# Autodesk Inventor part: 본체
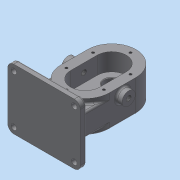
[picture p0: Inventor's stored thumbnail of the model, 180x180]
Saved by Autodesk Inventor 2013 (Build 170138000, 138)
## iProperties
Created: 2020-09
Part Number: 본체
Material: Generic
Document SubType Name: Modeling
Designer: Administrator
Density: 1 g/cm^3
Author: Administrator
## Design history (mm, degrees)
sketch "스케치1"
  geometry: L1 (-40, -62)-(40, -62); L2 (40, -62)-(40, 62); L3 (40, 62)-(-40, 62); L4 (-40, 62)-(-40, -62); L5 (-40, -62)-(40, 62); L6 (40, -62)-(-40, 62); 3 further points
  constraints: 12 end point, 3 midpoint, 2 parallel, 1 coincident, 1 horizontal, 1 perpendicular
  dimensions: "d0" = 124 distance of L1.end L2.end; "d2" = 80 distance of L1.start L1.end
extrude "돌출1" new body sketch "스케치1" distance "d3" = 53; taper "d4" = 0 deg
fillet "모깎기1" dims "d5" = 40
sketch "스케치2"
  geometry: L1 (0, 22)-(0, -22); L2 (24, 22)-(24, -22); L3 (-24, -22)-(-24, 22); A1 r 24 centre (0, -22) between (-24, -22) and (24, -22); A2 r 24 centre (0, 22) between (24, 22) and (-24, 22); 2 further points
  constraints: 6 end point, 4 point on circle, 3 coincident, 2 centre point, 2 parallel, 2 tangent, 1 midpoint, 1 vertical
  dimensions: "d7" = 44 distance of L1.start L1.end
extrude "돌출2" cut sketch "스케치2" distance "d11" = 29; taper "d12" = 0 deg
sketch "스케치3"
  geometry: L1 (-53, 44)-(0, 44) reference; L2 (0, 0)-(0, 44) reference; L3 (-53, 0)-(-53, 44) reference; C1 r 11 at (-39, 22); 3 further points
  constraints: 2 midpoint, 1 centre point, 1 horizontal alignment
  dimensions: "d13" = 22 diameter of C1; "d63" = 14 distance from line of L3 C1.centre
extrude "돌출3" join sketch "스케치3" distance "d15" = 10; taper "d16" = 0 deg
sketch "스케치4"
  geometry: L1 (0, 44)-(53, 44) reference; L2 (0, 44)-(0, 0) reference; L3 (53, 44)-(53, 0) reference; C1 r 11 at (39, 22); 3 further points
  constraints: 2 midpoint, 1 centre point, 1 horizontal alignment
  dimensions: "d17" = 22 diameter of C1; "d64" = 14 distance from line of L3 C1.centre
extrude "돌출4" join sketch "스케치4" distance "d19" = 10; taper "d20" = 0 deg
sketch "스케치5"
  geometry: L1 (-40, -22)-(-40, 22) reference; L2 (-40, 0)-(39.368, 0); C1 r 19 at (0, 22); 1 further point
  constraints: 2 end point, 1 centre point, 1 midpoint, 1 perpendicular
  dimensions: "d21" = 38 diameter of C1; "d23" = 22 distance from line of C1.centre L2
extrude "돌출5" join sketch "스케치5" distance "d24" = 17; taper "d25" = 0 deg
node "작업 평면1"
sketch "스케치6"
  geometry: L1 (-19, -17)-(19, -17) reference; L2 (-60, 83)-(-60, -17); L3 (-60, -17)-(60, -17); L4 (60, -17)-(60, 83); L5 (60, 83)-(-60, 83); L6 (-60, 83)-(60, -17); L7 (-60, -17)-(60, 83); 5 further points
  constraints: 12 end point, 5 midpoint, 2 parallel, 2 perpendicular, 1 coincident, 1 vertical alignment
  dimensions: "d27" = 120 distance of L4.end L2.start; "d29" = 100 distance of L3.end L4.end
extrude "돌출6" join sketch "스케치6" distance "d30" = 10; taper "d31" = 0 deg
sketch "스케치7"
  geometry: L1 (40, -53)-(40, 0) reference; L2 (-40, 0)-(-40, -53) reference; L3 (-40, -45)-(40, -45); L4 (40, -45)-(40, -8); L5 (40, -8)-(-40, -8); L6 (-40, -8)-(-40, -45); L7 (-40, -45)-(40, -8); L8 (40, -45)-(-40, -8); L9 (60, 17)-(-60, 17) reference; 3 further points
  constraints: 12 end point, 4 midpoint, 2 parallel, 2 perpendicular, 1 vertical alignment
  dimensions: "d35" = 25 distance between parallel lines of L9 L5; "d36" = 80 distance of L4.end L5.end; "d37" = 37 distance of L3.end L4.end
extrude "돌출7" join sketch "스케치7" stored distance "d38" = 10; taper "d39" = 0 deg
fillet "모깎기2" dims "d40" = 10
fillet "모깎기3" dims "d41" = 3
fillet "모깎기4" dims "d42" = 3
fillet "모깎기5" dims "d43" = 3
fillet "모깎기6" dims "d44" = 3
fillet "모깎기7" dims "d45" = 3
sketch "스케치8"
  geometry: L1 (0, 22)-(0, -22); C1 r 12.5 at (0, -22); C2 r 12.5 at (0, 22); 2 further points
  constraints: 3 coincident, 2 centre point, 2 end point, 1 midpoint, 1 vertical
  dimensions: "d46" = 44 distance of L1.start L1.end; "d48" = 25 diameter of C1; "d49" = 25 diameter of C2
extrude "돌출8" cut sketch "스케치8" distance "d50" = 15; taper "d51" = 0 deg
sketch "스케치9"
  geometry: C1 r 19 at (0, 0) reference; C2 r 14 at (0, 0); 1 further point
  constraints: 1 centre point, 1 coincident
  dimensions: "d52" = 28 diameter of C2
extrude "돌출9" cut sketch "스케치9" distance "d54" = 7.3; taper "d55" = 0 deg
chamfer "모따기1" distance "d56" = 0.7; stored, may be unused: second distance "d57" = 2, angle "d58" = 30 deg
sketch "스케치10"
  geometry: C1 r 19 at (0, 0) reference; C2 r 8.5 at (0, 0); 1 further point
  constraints: 1 centre point, 1 coincident
  dimensions: "d59" = 17 diameter of C2
extrude "돌출10" cut sketch "스케치10" stored distance "d61" = 7.3; taper "d62" = 0 deg
sketch "스케치11"
  geometry: C1 r 11 at (0, 0) reference; 2 further points
  constraints: 1 coincident
hole "구멍1" sketch "스케치11" at (0, 0) diameter "d65" = 8.376; stored, may be unused: countersink angle "d69" = 90 deg, drill point angle "d71" = 118 deg; dims "d66" = 30, "d67" = 4, "d68" = 2, "d70" = 31
sketch "스케치12"
  geometry: C1 r 11 at (0, 0) reference; 2 further points
  constraints: 1 coincident
hole "구멍2" sketch "스케치12" at (0, 0) diameter "d72" = 8.376; stored, may be unused: countersink angle "d76" = 90 deg, drill point angle "d78" = 118 deg; dims "d73" = 30, "d74" = 4, "d75" = 2, "d77" = 31
fillet "모깎기8" dims "d79" = 0.5
chamfer "모따기2" distance "d80" = 1; stored, may be unused: second distance "d81" = 2, angle "d82" = 30 deg
hole "구멍3" diameter "d85" = 9; stored, may be unused: countersink angle "d89" = 90 deg, drill point angle "d91" = 0 deg; dims "d83" = 10, "d84" = 10, "d86" = 30, "d87" = 4, "d88" = 2, "d90" = 31
hole "구멍4" diameter "d94" = 9; stored, may be unused: countersink angle "d98" = 90 deg, drill point angle "d100" = 0 deg; dims "d92" = 10, "d93" = 10, "d95" = 30, "d96" = 4, "d97" = 2, "d99" = 31
hole "구멍5" diameter "d103" = 9; stored, may be unused: countersink angle "d107" = 90 deg, drill point angle "d109" = 0 deg; dims "d101" = 10, "d102" = 10, "d104" = 30, "d105" = 4, "d106" = 2, "d108" = 31
hole "구멍6" diameter "d112" = 9; stored, may be unused: countersink angle "d116" = 90 deg, drill point angle "d118" = 0 deg; dims "d110" = 10, "d111" = 10, "d113" = 30, "d114" = 4, "d115" = 2, "d117" = 31
sketch "스케치13"
  geometry: A1 r 24 centre (0, 22) between (24, 22) and (-24, 22) reference; A2 r 31 centre (0, 22) between (0, 53) and (31, 22); A3 r 24 centre (0, -22) between (-24, -22) and (24, -22) reference; A4 r 31 centre (0, -22) between (31, -22) and (-31, -22); 3 further points
  constraints: 6 point on circle, 4 horizontal alignment, 2 centre point, 2 coincident, 2 vertical alignment
  dimensions: "d119" = 62 diameter of A2; "d123" = 62 diameter of A4
hole "구멍7" sketch "스케치13" at (0, 53), (31, 22), (-31, 22), (31, -22), (-31, -22), (0, -53) diameter "d124" = 4.134; stored, may be unused: countersink angle "d128" = 90 deg, drill point angle "d130" = 118 deg; dims "d125" = 10, "d126" = 4, "d127" = 2, "d129" = 12
fillet "모깎기9" dims "d131" = 3
sketch "스케치14"
  geometry: L1 (-50, -83)-(50, -83) reference; L2 (-60, 7)-(-60, -73) reference; 2 further points
  constraints: 1 other
  dimensions: "d132" = 12 distance from line of L1 point (0, -71); "d133" = 60 distance from line of L2 point (0, -71)
feature "엠보싱1" sketch "스케치14" dims "d11" = 29, "d134" = 0.5, "d135" = 0
node "솔리드1"
other parameters: "d9" = 48, "d10" = 48
